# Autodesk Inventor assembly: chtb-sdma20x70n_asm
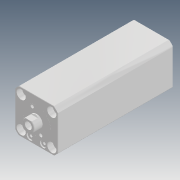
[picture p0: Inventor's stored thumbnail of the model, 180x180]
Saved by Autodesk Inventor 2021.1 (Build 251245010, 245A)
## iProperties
Created: 2018-05
Part Number: chtb-sdma20x70n_asm
Description: STEP AP214
Document SubType Name: Assembly
Designer: user
Title: chtb-sdma20x70n_asm.STEP
Revision Number: ÈÎºÎ
Sending System: SolidWorks 2016
Preprocessor: SwSTEP 2.0
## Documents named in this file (5)
- D:\Vault_2016\Projekty\Clamptek\Hydraulic\CHTB\CHTB-20\Inventor\CHTB-SDMA20x70N\chtb-sdma20x70n_asm.iam
- D:\Vault_2016\Projekty\Clamptek\Hydraulic\CHTB\CHTB-20\Inventor\CHTB-SDMA20x70N\CHTB-SDMA20X70NBT.ipt
- D:\Vault_2016\Projekty\Clamptek\Hydraulic\CHTB\CHTB-20\Inventor\CHTB-SDMA20x70N\CHTB-SDMA20X70NHSG.ipt
- D:\Vault_2016\Projekty\Clamptek\Hydraulic\CHTB\CHTB-20\Inventor\CHTB-SDMA20x70N\QG_3.ipt
- D:\Vault_2016\Projekty\Clamptek\Hydraulic\CHTB\CHTB-20\Inventor\CHTB-SDMA20x70N\socket set screw flat point_iso_ISO 4026 - M5 x 5-N.ipt
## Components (5 placed, 5 different names)
1. CHTB-SDMA20X70NBT_1
2. CHTB-SDMA20X70NHSG_2
3. QG_3_3
4. socket set screw flat point_iso_ISO 4026 - M5 x 5-N_4
5. socket set screw flat point_iso_ISO 4026 - M5 x 5-N_5
